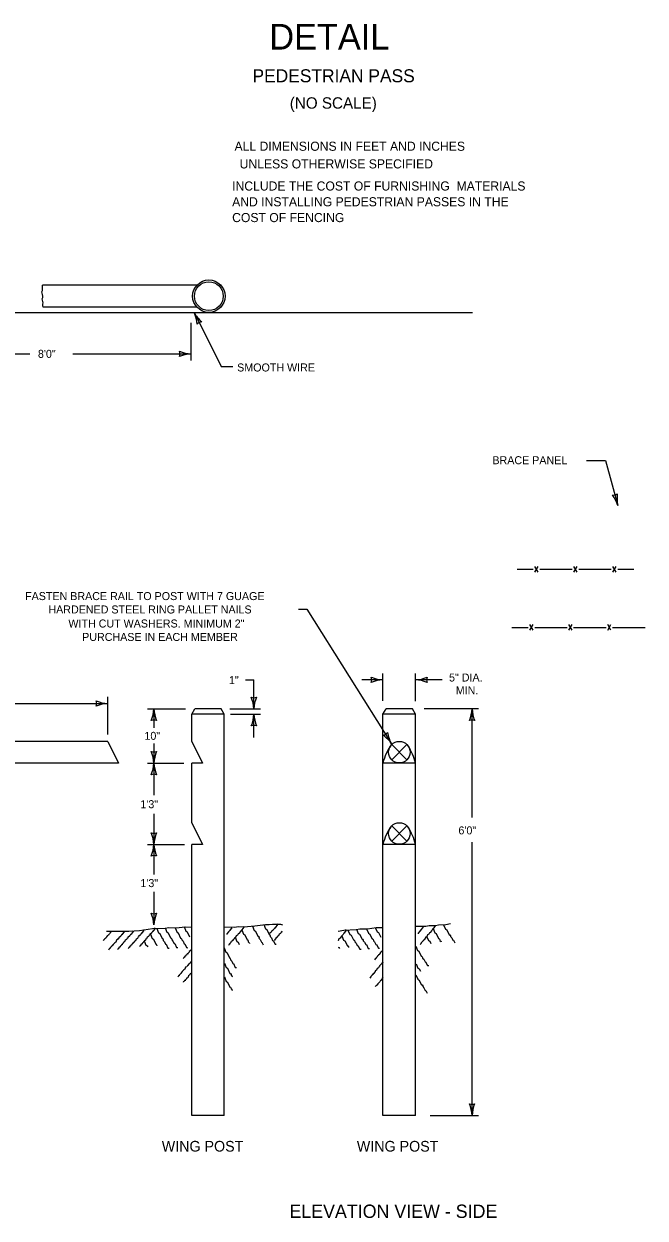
# Model space of a CAD drawing. Extents: x 49991 to 50288, y 49919 to 50011.
# Drawn here: x 50047.9 to 50057.52, y 49926.98 to 49945.45 of the extents above; entities that cross this region are included whole.
import ezdxf

# ---------------------------------------------------------------- set-up
doc = ezdxf.new("R2010")
doc.units = 0
for name, color, linetype in [('Level 1', 7, 'Continuous'), ('Level 2', 7, 'Continuous'), ('Level 3', 7, 'Continuous'), ('Level 5', 7, 'Continuous'), ('Level 7', 7, 'Continuous')]:
    doc.layers.add(name, color=color, linetype=linetype)

msp = doc.modelspace()

# ---------------------------------------------------------------- linework, layer by layer
at = {"layer": 'Level 1'}
for centre, radius, start, end in [((50050.99, 49941.248), 0.526, 210.01, 230.1935), ((50050.034, 49940.754), 0.551, 5.5723, 24.8222), ((50050.675, 49940.716), 0.13, 99.7883, 135.5107), ((50050.511, 49940.873), 0.526, 247.456, 267.6395), ((50050.186, 49940.347), 0.13, 342.1388, 17.8612), ((50050.517, 49939.796), 0.551, 92.8273, 112.0772), ((50057.014, 49938.293), 0.13, 267.1123, 302.8347), ((50056.568, 49937.832), 0.551, 17.8008, 37.0507), ((50057.606, 49938.115), 0.526, 172.4295, 192.613), ((50053.48, 49935.831), 0.526, 247.456, 267.6395), ((50053.154, 49935.306), 0.13, 342.1388, 17.8612), ((50053.485, 49934.755), 0.551, 92.8273, 112.0772), ((50053.934, 49935.856), 0.551, 272.8273, 292.0772), ((50053.939, 49934.78), 0.526, 67.456, 87.6395), ((50054.264, 49935.306), 0.13, 162.1388, 197.8612), ((50049.223, 49935.466), 0.526, 247.456, 267.6395), ((50048.898, 49934.941), 0.13, 342.1388, 17.8612), ((50049.229, 49934.39), 0.551, 92.8273, 112.0772), ((50051.461, 49935.16), 0.13, 252.1388, 287.8612), ((50050.91, 49934.829), 0.551, 2.8273, 22.0772), ((50051.986, 49934.835), 0.526, 157.456, 177.6395), ((50049.387, 49934.878), 0.526, 337.456, 357.6395), ((50050.464, 49934.884), 0.551, 182.8273, 202.0772), ((50050.935, 49934.795), 0.526, 337.456, 357.6395), ((50052.011, 49934.8), 0.551, 182.8273, 202.0772), ((50054.312, 49934.878), 0.526, 337.456, 357.6395), ((50055.388, 49934.884), 0.551, 182.8273, 202.0772), ((50049.913, 49934.553), 0.13, 72.1388, 107.8612), ((50051.461, 49934.47), 0.13, 72.1388, 107.8612), ((50054.838, 49934.553), 0.13, 72.1388, 107.8612), ((50053.431, 49934.576), 0.13, 283.7835, 319.5058), ((50053.136, 49934.006), 0.551, 34.472, 53.7218), ((50054.049, 49934.575), 0.526, 189.1007, 209.2842), ((50049.913, 49934.322), 0.13, 252.1388, 287.8612), ((50049.362, 49933.992), 0.551, 2.8273, 22.0772), ((50050.439, 49933.997), 0.526, 157.456, 177.6395), ((50049.387, 49934.04), 0.526, 337.456, 357.6395), ((50050.464, 49934.046), 0.551, 182.8273, 202.0772), ((50049.913, 49933.715), 0.13, 72.1388, 107.8612), ((50049.913, 49933.065), 0.13, 252.1388, 287.8612), ((50049.362, 49932.734), 0.551, 2.8273, 22.0772), ((50050.439, 49932.74), 0.526, 157.456, 177.6395), ((50049.387, 49932.783), 0.526, 337.456, 357.6395), ((50050.464, 49932.789), 0.551, 182.8273, 202.0772), ((50049.913, 49932.458), 0.13, 72.1388, 107.8612), ((50049.913, 49931.819), 0.13, 252.1388, 287.8612), ((50049.362, 49931.489), 0.551, 2.8273, 22.0772), ((50050.439, 49931.494), 0.526, 157.456, 177.6395), ((50054.838, 49928.874), 0.13, 252.1388, 287.8612), ((50054.287, 49928.543), 0.551, 2.8273, 22.0772), ((50055.363, 49928.549), 0.526, 157.456, 177.6395)]:
    msp.add_arc(centre, radius, start, end, dxfattribs=at)
at = {"layer": 'Level 3'}
for p, q in [((50049.913, 49934.857), (50049.913, 49934.566)), ((50049.913, 49934.319), (50049.913, 49934.019)), ((50049.913, 49934.019), (50049.913, 49933.52)), ((50049.913, 49933.234), (50049.913, 49932.762)), ((50049.913, 49932.762), (50049.913, 49932.297)), ((50049.913, 49932.03), (50049.913, 49931.516))]:
    msp.add_line(p, q, dxfattribs=at)
at = {"layer": 'Level 5'}
for points in [[(50049.245, 49931.416), (50049.25, 49931.411), (50049.235, 49931.393), (50049.235, 49931.388), (50049.23, 49931.388), (50049.225, 49931.379), (50049.21, 49931.365), (50049.21, 49931.36), (50049.205, 49931.36), (50049.2, 49931.351), (50049.19, 49931.346), (50049.185, 49931.332), (50049.175, 49931.327), (50049.175, 49931.322), (50049.165, 49931.313), (50049.165, 49931.308), (50049.16, 49931.308), (50049.155, 49931.299), (50049.15, 49931.299), (50049.15, 49931.294), (50049.14, 49931.285), (50049.14, 49931.28), (50049.135, 49931.28), (50049.13, 49931.271)], [(50049.178, 49931.419), (50049.525, 49931.418), (50049.69, 49931.431), (50049.893, 49931.463), (50050.086, 49931.467), (50050.144, 49931.475), (50050.26, 49931.471), (50050.395, 49931.486), (50050.494, 49931.483)], [(50049.443, 49931.42), (50049.453, 49931.41), (50049.422, 49931.372), (50049.422, 49931.363), (50049.413, 49931.363), (50049.402, 49931.344), (50049.372, 49931.316), (50049.372, 49931.306), (50049.362, 49931.307), (50049.352, 49931.288), (50049.333, 49931.279), (50049.322, 49931.25), (50049.302, 49931.241), (50049.302, 49931.232), (50049.282, 49931.213), (50049.282, 49931.203), (50049.272, 49931.203), (50049.262, 49931.184), (50049.253, 49931.185), (50049.252, 49931.175), (50049.232, 49931.157), (50049.232, 49931.147), (50049.222, 49931.147), (50049.212, 49931.128)], [(50049.581, 49931.423), (50049.59, 49931.413), (50049.56, 49931.375), (50049.56, 49931.366), (50049.55, 49931.366), (50049.54, 49931.347), (50049.51, 49931.319), (50049.51, 49931.309), (50049.5, 49931.309), (50049.49, 49931.291), (50049.47, 49931.282), (50049.46, 49931.253), (50049.44, 49931.244), (50049.44, 49931.234), (50049.42, 49931.216), (50049.42, 49931.206), (50049.41, 49931.206), (50049.4, 49931.187), (50049.39, 49931.188), (50049.39, 49931.178), (50049.37, 49931.159), (50049.37, 49931.15), (50049.36, 49931.15), (50049.35, 49931.131)], [(50049.747, 49931.439), (50049.757, 49931.429), (50049.727, 49931.392), (50049.726, 49931.382), (50049.717, 49931.382), (50049.707, 49931.363), (50049.677, 49931.335), (50049.677, 49931.326), (50049.667, 49931.326), (50049.657, 49931.307), (50049.637, 49931.298), (50049.626, 49931.269), (50049.607, 49931.26), (50049.607, 49931.251), (50049.587, 49931.232), (50049.586, 49931.223), (50049.577, 49931.223), (50049.567, 49931.204), (50049.557, 49931.204), (50049.556, 49931.194), (50049.537, 49931.176), (50049.536, 49931.166), (50049.527, 49931.167), (50049.516, 49931.148)], [(50049.922, 49931.47), (50049.931, 49931.46), (50049.901, 49931.422), (50049.901, 49931.413), (50049.891, 49931.413), (50049.881, 49931.394), (50049.852, 49931.366), (50049.851, 49931.356), (50049.841, 49931.357), (50049.831, 49931.338), (50049.811, 49931.329), (50049.801, 49931.3), (50049.782, 49931.291), (50049.781, 49931.281), (50049.761, 49931.263), (50049.761, 49931.253), (50049.751, 49931.253), (50049.741, 49931.235), (50049.731, 49931.235), (50049.731, 49931.225), (50049.711, 49931.206), (50049.711, 49931.197), (50049.701, 49931.197), (50049.691, 49931.178)], [(50049.958, 49931.461), (50049.985, 49931.393), (50050.004, 49931.383), (50050.04, 49931.305), (50050.05, 49931.304), (50050.059, 49931.285), (50050.058, 49931.275), (50050.077, 49931.255), (50050.095, 49931.216), (50050.104, 49931.216), (50050.131, 49931.157), (50050.151, 49931.156)], [(50050.089, 49931.472), (50050.115, 49931.403), (50050.134, 49931.393), (50050.17, 49931.315), (50050.18, 49931.315), (50050.189, 49931.295), (50050.189, 49931.285), (50050.207, 49931.265), (50050.226, 49931.226), (50050.235, 49931.226), (50050.262, 49931.167), (50050.282, 49931.167)], [(50050.245, 49931.469), (50050.272, 49931.401), (50050.291, 49931.391), (50050.327, 49931.312), (50050.337, 49931.312), (50050.346, 49931.293), (50050.345, 49931.283), (50050.364, 49931.263), (50050.382, 49931.224), (50050.392, 49931.223), (50050.419, 49931.165), (50050.438, 49931.164)], [(50050.381, 49931.489), (50050.408, 49931.421), (50050.426, 49931.41), (50050.463, 49931.332)], [(50051.006, 49931.486), (50051.167, 49931.481), (50051.215, 49931.489), (50051.311, 49931.486), (50051.36, 49931.494), (50051.476, 49931.5), (50051.64, 49931.524), (50051.698, 49931.522), (50051.747, 49931.53), (50051.872, 49931.526), (50051.903, 49931.518)], [(50051.111, 49931.483), (50051.12, 49931.473), (50051.09, 49931.435), (50051.09, 49931.426), (50051.081, 49931.426), (50051.07, 49931.407), (50051.04, 49931.379), (50051.04, 49931.37)], [(50051.297, 49931.489), (50051.306, 49931.479), (50051.276, 49931.441), (50051.276, 49931.432), (50051.266, 49931.432), (50051.256, 49931.413), (50051.226, 49931.385), (50051.226, 49931.376), (50051.216, 49931.376), (50051.206, 49931.357), (50051.186, 49931.348), (50051.176, 49931.319), (50051.156, 49931.31), (50051.156, 49931.301), (50051.136, 49931.282), (50051.136, 49931.272), (50051.126, 49931.273), (50051.116, 49931.254), (50051.106, 49931.254), (50051.106, 49931.244), (50051.086, 49931.226), (50051.086, 49931.216), (50051.076, 49931.216), (50051.066, 49931.197)], [(50051.274, 49931.442), (50051.3, 49931.373), (50051.319, 49931.363), (50051.356, 49931.284), (50051.365, 49931.284), (50051.374, 49931.265), (50051.374, 49931.255), (50051.392, 49931.235), (50051.395, 49931.23)], [(50051.439, 49931.497), (50051.466, 49931.428), (50051.485, 49931.418), (50051.521, 49931.34), (50051.531, 49931.339), (50051.54, 49931.32), (50051.539, 49931.31), (50051.558, 49931.29), (50051.576, 49931.251), (50051.586, 49931.251), (50051.605, 49931.21)], [(50051.614, 49931.522), (50051.641, 49931.454), (50051.66, 49931.444), (50051.696, 49931.366), (50051.705, 49931.365), (50051.714, 49931.346), (50051.714, 49931.336), (50051.733, 49931.316), (50051.751, 49931.277), (50051.76, 49931.277), (50051.788, 49931.218), (50051.807, 49931.217)], [(50051.819, 49931.535), (50051.829, 49931.525), (50051.799, 49931.488), (50051.798, 49931.478), (50051.788, 49931.478), (50051.778, 49931.459), (50051.748, 49931.431), (50051.748, 49931.422), (50051.739, 49931.422), (50051.728, 49931.403), (50051.709, 49931.394), (50051.705, 49931.383)], [(50051.9, 49931.419), (50051.893, 49931.413), (50051.892, 49931.403), (50051.883, 49931.403), (50051.872, 49931.384), (50051.853, 49931.375), (50051.842, 49931.346), (50051.823, 49931.337), (50051.822, 49931.328), (50051.802, 49931.309), (50051.802, 49931.3), (50051.793, 49931.3), (50051.782, 49931.281), (50051.773, 49931.281), (50051.773, 49931.279)], [(50052.765, 49931.421), (50052.852, 49931.437), (50053.045, 49931.447), (50053.102, 49931.457), (50053.218, 49931.457), (50053.353, 49931.476), (50053.457, 49931.476)], [(50052.881, 49931.445), (50052.89, 49931.435), (50052.861, 49931.397), (50052.861, 49931.387), (50052.852, 49931.387), (50052.842, 49931.368), (50052.813, 49931.339), (50052.813, 49931.329), (50052.804, 49931.329), (50052.794, 49931.31), (50052.775, 49931.3), (50052.765, 49931.271), (50052.765, 49931.271)], [(50052.917, 49931.437), (50052.946, 49931.37), (50052.965, 49931.36), (50053.004, 49931.283), (50053.013, 49931.283), (50053.023, 49931.264), (50053.023, 49931.254), (50053.042, 49931.235), (50053.061, 49931.196), (50053.071, 49931.196), (50053.1, 49931.139), (50053.119, 49931.139)], [(50053.047, 49931.452), (50053.076, 49931.384), (50053.095, 49931.375), (50053.134, 49931.298), (50053.143, 49931.298), (50053.153, 49931.279), (50053.153, 49931.269), (50053.172, 49931.25), (50053.192, 49931.211), (50053.201, 49931.211), (50053.23, 49931.153), (50053.25, 49931.153)], [(50053.204, 49931.454), (50053.233, 49931.387), (50053.252, 49931.377), (50053.291, 49931.3), (50053.3, 49931.3), (50053.31, 49931.281), (50053.31, 49931.271), (50053.329, 49931.252), (50053.348, 49931.213), (50053.358, 49931.213), (50053.387, 49931.156), (50053.406, 49931.156)], [(50053.339, 49931.478), (50053.368, 49931.411), (50053.387, 49931.401), (50053.425, 49931.326)], [(50053.96, 49931.495), (50054.124, 49931.495), (50054.172, 49931.505), (50054.269, 49931.505), (50054.317, 49931.515), (50054.432, 49931.524), (50054.501, 49931.536)], [(50054.069, 49931.495), (50054.078, 49931.486), (50054.049, 49931.447), (50054.049, 49931.437), (50054.04, 49931.437), (50054.03, 49931.418), (50054.001, 49931.389), (50054.001, 49931.38)], [(50054.254, 49931.507), (50054.264, 49931.498), (50054.235, 49931.459), (50054.235, 49931.45), (50054.225, 49931.45), (50054.216, 49931.43), (50054.187, 49931.401), (50054.187, 49931.392), (50054.177, 49931.392), (50054.167, 49931.372), (50054.148, 49931.363), (50054.138, 49931.334), (50054.119, 49931.324), (50054.119, 49931.315), (50054.1, 49931.295), (50054.1, 49931.286), (50054.09, 49931.286), (50054.081, 49931.267), (50054.071, 49931.267), (50054.071, 49931.257), (50054.052, 49931.237), (50054.052, 49931.228), (50054.042, 49931.228), (50054.033, 49931.208)], [(50054.233, 49931.459), (50054.261, 49931.392), (50054.281, 49931.382), (50054.319, 49931.305), (50054.329, 49931.305), (50054.338, 49931.286), (50054.338, 49931.276), (50054.358, 49931.257), (50054.36, 49931.252)], [(50054.396, 49931.519), (50054.425, 49931.452), (50054.445, 49931.442), (50054.483, 49931.365), (50054.493, 49931.365), (50054.502, 49931.346), (50054.502, 49931.336), (50054.522, 49931.317), (50054.541, 49931.279), (50054.551, 49931.279), (50054.571, 49931.238)], [(50049.764, 49931.272), (50049.791, 49931.204), (50049.81, 49931.194), (50049.817, 49931.178)], [(50049.859, 49931.375), (50049.886, 49931.307), (50049.905, 49931.297), (50049.941, 49931.218), (50049.95, 49931.218), (50049.959, 49931.199), (50049.959, 49931.19)], [(50051.171, 49931.329), (50051.198, 49931.261), (50051.217, 49931.25), (50051.235, 49931.211)], [(50052.82, 49931.348), (50052.85, 49931.281), (50052.869, 49931.271), (50052.907, 49931.194), (50052.917, 49931.194), (50052.927, 49931.175), (50052.927, 49931.167)], [(50054.134, 49931.343), (50054.163, 49931.276), (50054.182, 49931.266), (50054.201, 49931.228)], [(50050.483, 49931.129), (50050.477, 49931.113), (50050.457, 49931.104), (50050.457, 49931.095), (50050.437, 49931.076), (50050.437, 49931.066), (50050.427, 49931.067), (50050.417, 49931.048), (50050.407, 49931.048), (50050.407, 49931.038), (50050.387, 49931.02), (50050.387, 49931.01), (50050.377, 49931.01), (50050.367, 49930.991)], [(50051, 49931.163), (50051.027, 49931.095), (50051.046, 49931.085), (50051.082, 49931.006), (50051.091, 49931.006), (50051.1, 49930.987), (50051.1, 49930.977), (50051.119, 49930.957), (50051.137, 49930.918), (50051.147, 49930.917), (50051.173, 49930.859), (50051.193, 49930.858)], [(50052.765, 49931.171), (50052.777, 49931.165), (50052.785, 49931.15)], [(50053.44, 49931.115), (50053.435, 49931.099), (50053.416, 49931.089), (50053.416, 49931.08), (50053.397, 49931.06), (50053.397, 49931.051), (50053.387, 49931.051), (50053.377, 49931.032), (50053.368, 49931.032), (50053.368, 49931.022), (50053.348, 49931.003), (50053.348, 49930.993), (50053.339, 49930.993), (50053.329, 49930.974)], [(50053.965, 49931.187), (50053.994, 49931.12), (50054.013, 49931.11), (50054.052, 49931.033), (50054.062, 49931.033), (50054.071, 49931.014), (50054.071, 49931.004), (50054.09, 49930.985), (50054.11, 49930.946), (50054.119, 49930.946), (50054.148, 49930.888), (50054.167, 49930.888)], [(50050.493, 49930.95), (50050.493, 49930.945), (50050.483, 49930.945), (50050.473, 49930.926), (50050.443, 49930.898), (50050.442, 49930.889), (50050.433, 49930.889), (50050.423, 49930.87), (50050.403, 49930.861), (50050.393, 49930.832), (50050.373, 49930.823), (50050.373, 49930.814), (50050.353, 49930.795), (50050.353, 49930.785), (50050.343, 49930.785), (50050.333, 49930.767), (50050.323, 49930.767), (50050.323, 49930.757), (50050.303, 49930.739), (50050.303, 49930.729), (50050.293, 49930.729), (50050.283, 49930.71)], [(50051.007, 49930.924), (50051.034, 49930.855), (50051.053, 49930.845), (50051.089, 49930.766), (50051.099, 49930.766), (50051.108, 49930.747), (50051.107, 49930.737), (50051.126, 49930.717), (50051.128, 49930.712)], [(50053.456, 49930.936), (50053.456, 49930.931), (50053.446, 49930.931), (50053.436, 49930.912), (50053.407, 49930.883), (50053.407, 49930.873), (50053.398, 49930.873), (50053.388, 49930.854), (50053.369, 49930.844), (50053.359, 49930.815), (50053.34, 49930.806), (50053.34, 49930.796), (50053.321, 49930.777), (50053.321, 49930.767), (50053.311, 49930.767), (50053.301, 49930.748), (50053.292, 49930.748), (50053.292, 49930.738), (50053.273, 49930.719), (50053.273, 49930.709), (50053.263, 49930.709), (50053.253, 49930.69)], [(50053.971, 49930.914), (50054, 49930.847), (50054.019, 49930.837), (50054.038, 49930.799)], [(50050.494, 49930.773), (50050.487, 49930.766), (50050.486, 49930.756), (50050.477, 49930.757), (50050.466, 49930.738), (50050.447, 49930.729), (50050.436, 49930.7), (50050.417, 49930.691), (50050.416, 49930.681), (50050.397, 49930.663), (50050.396, 49930.653), (50050.387, 49930.654), (50050.376, 49930.635), (50050.367, 49930.635), (50050.367, 49930.633)], [(50051.007, 49930.711), (50051.034, 49930.643), (50051.053, 49930.633), (50051.089, 49930.554), (50051.099, 49930.554), (50051.108, 49930.535), (50051.107, 49930.525), (50051.126, 49930.505), (50051.128, 49930.5)], [(50053.448, 49930.712), (50053.457, 49930.702), (50053.429, 49930.664), (50053.429, 49930.654), (50053.419, 49930.654), (50053.409, 49930.635), (50053.38, 49930.606), (50053.38, 49930.596), (50053.371, 49930.596), (50053.361, 49930.577), (50053.342, 49930.567), (50053.338, 49930.556)], [(50053.967, 49930.745), (50053.996, 49930.677), (50054.015, 49930.668), (50054.054, 49930.591), (50054.064, 49930.591), (50054.073, 49930.572), (50054.073, 49930.562), (50054.093, 49930.543), (50054.112, 49930.504), (50054.122, 49930.504), (50054.142, 49930.463)]]:
    msp.add_lwpolyline(points, dxfattribs=at)
at = {"layer": 'Level 7'}
for p, q in [((50050.577, 49941.407), (50048.191, 49941.407)), ((50050.577, 49941.071), (50048.201, 49941.071)), ((50046.071, 49940.985), (50050.764, 49940.985)), ((50050.49, 49940.246), (50050.49, 49940.825)), ((50050.535, 49940.985), (50050.961, 49940.147)), ((50050.764, 49940.985), (50054.846, 49940.985)), ((50046.326, 49940.347), (50047.992, 49940.347)), ((50048.661, 49940.347), (50050.49, 49940.347)), ((50051.136, 49940.147), (50050.961, 49940.147)), ((50056.609, 49938.699), (50056.903, 49938.699)), ((50056.903, 49938.699), (50057.093, 49938)), ((50055.809, 49936.973), (50055.86, 49937.06)), ((50055.86, 49936.973), (50055.809, 49937.06)), ((50056.413, 49936.973), (50056.463, 49937.06)), ((50056.463, 49936.973), (50056.413, 49937.06)), ((50057.016, 49936.973), (50057.066, 49937.06)), ((50057.066, 49936.973), (50057.016, 49937.06)), ((50052.152, 49936.399), (50052.282, 49936.399)), ((50052.282, 49936.399), (50053.59, 49934.318)), ((50055.73, 49936.072), (50055.781, 49936.159)), ((50055.781, 49936.072), (50055.73, 49936.159)), ((50056.334, 49936.072), (50056.384, 49936.159)), ((50056.384, 49936.072), (50056.334, 49936.159)), ((50056.937, 49936.072), (50056.987, 49936.159)), ((50056.987, 49936.072), (50056.937, 49936.159)), ((50051.331, 49935.306), (50051.461, 49935.306)), ((50051.461, 49934.857), (50051.461, 49935.306)), ((50053.458, 49935.306), (50053.13, 49935.306)), ((50053.458, 49934.98), (50053.458, 49935.406)), ((50053.961, 49934.975), (50053.961, 49935.406)), ((50054.377, 49935.306), (50053.961, 49935.306)), ((50047.1, 49934.941), (50049.201, 49934.941)), ((50049.201, 49934.462), (50049.201, 49935.041)), ((50049.812, 49934.857), (50050.404, 49934.857)), ((50050.498, 49934.773), (50050.546, 49934.857)), ((50051.001, 49934.773), (50050.498, 49934.773)), ((50050.498, 49934.354), (50050.498, 49934.773)), ((50050.953, 49934.857), (50050.546, 49934.857)), ((50051.001, 49934.773), (50050.953, 49934.857)), ((50051.001, 49928.571), (50051.001, 49934.773)), ((50051.089, 49934.857), (50051.561, 49934.857)), ((50051.099, 49934.773), (50051.561, 49934.773)), ((50051.461, 49934.413), (50051.461, 49934.773)), ((50053.458, 49934.773), (50053.506, 49934.857)), ((50053.961, 49934.773), (50053.458, 49934.773)), ((50053.458, 49928.571), (50053.458, 49934.773)), ((50053.913, 49934.857), (50053.506, 49934.857)), ((50053.961, 49934.773), (50053.913, 49934.857)), ((50053.961, 49928.571), (50053.961, 49934.773)), ((50054.938, 49934.857), (50054.098, 49934.857)), ((50054.838, 49933.179), (50054.838, 49934.857)), ((50049.201, 49934.354), (50041.489, 49934.354)), ((50049.201, 49934.354), (50049.368, 49934.019)), ((50050.498, 49934.354), (50050.665, 49934.019)), ((50053.593, 49934.069), (50053.83, 49934.305)), ((50053.83, 49934.069), (50053.593, 49934.305)), ((50049.368, 49934.019), (50041.322, 49934.019)), ((50049.812, 49934.019), (50050.377, 49934.019)), ((50050.665, 49934.019), (50050.498, 49934.019)), ((50050.498, 49933.097), (50050.498, 49934.019)), ((50053.961, 49934.019), (50053.458, 49934.019)), ((50050.498, 49933.097), (50050.665, 49932.762)), ((50053.593, 49932.811), (50053.83, 49933.048)), ((50053.83, 49932.811), (50053.593, 49933.048)), ((50049.812, 49932.762), (50050.386, 49932.762)), ((50050.665, 49932.762), (50050.498, 49932.762)), ((50050.498, 49928.571), (50050.498, 49932.762)), ((50053.961, 49932.762), (50053.458, 49932.762)), ((50054.838, 49928.571), (50054.838, 49932.795)), ((50051.001, 49928.571), (50050.498, 49928.571)), ((50053.961, 49928.571), (50053.458, 49928.571)), ((50054.19, 49928.571), (50054.938, 49928.571))]:
    msp.add_line(p, q, dxfattribs=at)
for points in [[(50048.201, 49941.071), (50048.196, 49941.092), (50048.196, 49941.114), (50048.201, 49941.135), (50048.196, 49941.156), (50048.188, 49941.176), (50048.184, 49941.197), (50048.192, 49941.216), (50048.192, 49941.241), (50048.188, 49941.262), (50048.182, 49941.285), (50048.177, 49941.308), (50048.188, 49941.326), (50048.188, 49941.353), (50048.191, 49941.375), (50048.191, 49941.406), (50048.191, 49941.407)], [(50055.533, 49937.016), (50055.784, 49937.016)], [(50055.885, 49937.016), (50056.136, 49937.016)], [(50056.136, 49937.016), (50056.388, 49937.016)], [(50056.488, 49937.016), (50056.74, 49937.016)], [(50056.74, 49937.016), (50056.991, 49937.016)], [(50057.092, 49937.016), (50057.343, 49937.016)], [(50055.454, 49936.115), (50055.705, 49936.115)], [(50055.806, 49936.115), (50056.057, 49936.115)], [(50056.057, 49936.115), (50056.309, 49936.115)], [(50056.409, 49936.115), (50056.661, 49936.115)], [(50056.661, 49936.115), (50056.912, 49936.115)], [(50057.013, 49936.115), (50057.264, 49936.115)], [(50057.264, 49936.115), (50057.515, 49936.115)]]:
    msp.add_lwpolyline(points, dxfattribs=at)
for centre, radius in [((50050.764, 49941.239), 0.251), ((50050.764, 49941.239), 0.222), ((50053.712, 49934.187), 0.167), ((50053.712, 49932.93), 0.167)]:
    msp.add_circle(centre, radius, dxfattribs=at)
for centre, radius, start, end in [((50054.181, 49933.857), 0.741, 142.8422, 167.3608), ((50053.184, 49933.847), 0.795, 12.4495, 33.244), ((50054.181, 49932.599), 0.741, 142.8422, 167.3608), ((50053.184, 49932.59), 0.795, 12.4495, 33.244)]:
    msp.add_arc(centre, radius, start, end, dxfattribs=at)

# ---------------------------------------------------------------- texts
at = {"layer": 'Level 1'}
for s, height, p in [('DETAIL', 0.3968, (50051.7, 49945.052)), ('INCLUDE THE COST OF FURNISHING  MATERIALS', 0.1408, (50051.124, 49942.872)), ('AND INSTALLING PEDESTRIAN PASSES IN THE', 0.1408, (50051.124, 49942.628)), ('COST OF FENCING', 0.1408, (50051.124, 49942.384))]:
    msp.add_text(s, height=height, dxfattribs=at).set_placement(p)
at = {"layer": 'Level 2'}
for s, height, p in [('8\'0"', 0.1237, (50048.119, 49940.285)), ('BRACE PANEL', 0.12374, (50055.152, 49938.64)), ('1"', 0.1237, (50051.075, 49935.239)), ('5" DIA.', 0.1237, (50054.481, 49935.28)), ('MIN.', 0.1237, (50054.585, 49935.083)), ('10"', 0.1237, (50049.767, 49934.378)), ('1\'3"', 0.1237, (50049.704, 49933.321)), ('6\'0"', 0.1237, (50054.626, 49932.916)), ('1\'3"', 0.1237, (50049.704, 49932.101))]:
    msp.add_text(s, height=height, rotation=360, dxfattribs=at).set_placement(p)
for s, height, p in [('SMOOTH WIRE', 0.12374, (50051.202, 49940.074)), ('FASTEN BRACE RAIL TO POST WITH 7 GUAGE', 0.12374, (50047.92, 49936.539)), ('HARDENED STEEL RING PALLET NAILS', 0.12374, (50048.281, 49936.332)), ('WITH CUT WASHERS. MINIMUM 2"', 0.12374, (50048.59, 49936.115)), ('PURCHASE IN EACH MEMBER', 0.12374, (50048.803, 49935.907)), ('WING POST', 0.165, (50050.035, 49928.011)), ('WING POST', 0.165, (50053.054, 49928.011)), ('ELEVATION VIEW - SIDE', 0.20623, (50052.01, 49926.985))]:
    msp.add_text(s, height=height, dxfattribs=at).set_placement(p)
at = {"layer": 'Level 7'}
for s, height, p in [('PEDESTRIAN PASS', 0.20115, (50051.439, 49944.546)), ('(NO SCALE)', 0.176, (50052.016, 49944.138)), ('ALL DIMENSIONS IN FEET AND INCHES', 0.1408, (50051.161, 49943.487)), ('UNLESS OTHERWISE SPECIFIED', 0.1408, (50051.24, 49943.214))]:
    msp.add_text(s, height=height, dxfattribs=at).set_placement(p)

doc.saveas('drawing.dxf')
